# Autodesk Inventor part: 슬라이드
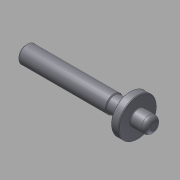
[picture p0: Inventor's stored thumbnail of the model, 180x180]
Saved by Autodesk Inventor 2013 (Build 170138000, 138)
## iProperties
Company: 한국ATC센터
Created: 2015-12
Part Number: 슬라이드
Document SubType Name: Modeling
Designer: mdu
Density: 7.86 g/cm^3
Mass: 70.6636 g
Surface Area: 37.2302 cm^2
Volume: 8.99028 cm^3
Material: 강철, 연강
Author: mdu
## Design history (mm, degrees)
sketch "스케치1"
  geometry: L1 (-35, 0)-(35, 0); L2 (35, 0)-(35, 12); L3 (35, 12)-(30, 12); L4 (30, 12)-(30, 5); L5 (30, 5)-(20.5, 5); L6 (20.5, 5)-(20, 5.5); L7 (20, 5.5)-(-35, 5.5); L8 (-35, 5.5)-(-35, 0); 1 further point
  constraints: 16 end point, 4 parallel, 2 midpoint, 2 perpendicular, 1 horizontal
  dimensions: "d0" = 70 distance of L1.start L1.end; "d1" = 11 diameter of L7 L1; "d2" = 24 diameter of L3 L1; "d3" = 5 distance of L2.end L3.end; "d4" = 10 diameter of L5 L1; "d5" = 135 deg angle of L6 L5; "d6" = 15 distance from line of L2 L6.end
revolve "회전1" sketch "스케치1" stored, may be unused: angle "d7" = 90 deg
chamfer "모따기1" distance "d8" = 1; stored, may be unused: second distance "d9" = 2, angle "d10" = 45 deg
fillet "모깎기1" dims "d11" = 0.5
sketch "스케치2"
  geometry: C1 r 11.5 at (0, 0) reference; C2 r 5 at (0, 0)
  constraints: 1 centre point, 1 coincident
  dimensions: "d12" = 10 diameter of C2
extrude "돌출1" join sketch "스케치2" distance "d13" = 10; taper "d14" = 0 deg
fillet "모깎기2" dims "d16" = 0.5
fillet "모깎기3" dims "d17" = 3
node "솔리드1"
